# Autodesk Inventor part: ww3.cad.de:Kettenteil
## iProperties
Created: 2005-10
Document SubType Name: Modeling
Designer: Michalik
Achsabstand: 125,000 mm
Author: Michalik
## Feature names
1. Extrusion1
2. Bohrung1 [Hole]
3. Extrusion2
4. Spiegeln1 [Mirror]
5. Extrusion3
